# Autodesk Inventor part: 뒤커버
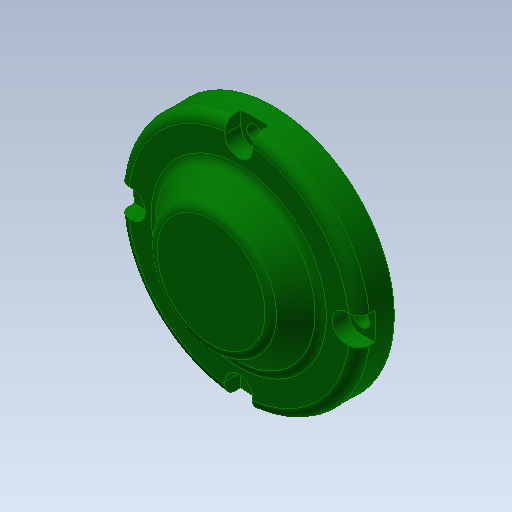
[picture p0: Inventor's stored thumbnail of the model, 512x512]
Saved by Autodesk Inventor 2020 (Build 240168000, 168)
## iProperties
Created: 2017-08
Part Number: 뒤커버
Material: 알루미늄 6061
Document SubType Name: Modeling
Designer: mduedu
Density: 1 g/cm^3
Appearance: 진녹색
Author: mduedu
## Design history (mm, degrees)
sketch "스케치1"
  geometry: C1 r 35 at (0, 0); 1 further point
  constraints: 1 centre point, 1 coincident
  dimensions: "d0" = 70 diameter of C1
extrude "돌출1" new body sketch "스케치1" distance "d1" = 10; taper "d2" = 0 deg
sketch "스케치2"
  geometry: C1 r 24 at (0, 0); 1 further point
  constraints: 1 centre point, 1 coincident
  dimensions: "d3" = 48 diameter of C1
node "작업 평면1"
sketch "스케치3"
  geometry: C1 r 17 at (0, 0); 1 further point
  constraints: 1 centre point, 1 coincident
  dimensions: "d5" = 34 diameter of C1
feature "로프트1" sketch "스케치3" dims "d6" = 0, "d7" = 90 deg, "d8" = 0, "d9" = 90 deg
sketch "스케치4"
  geometry: C1 r 24 at (0, 0) reference; 1 further point
extrude "돌출2" join sketch "스케치4" distance "d10" = 8; taper "d11" = 0 deg
hole "구멍1" diameter "d14" = 40; stored, may be unused: countersink angle "d18" = 90 deg, drill point angle "d20" = 0 deg; dims "d12" = 10, "d13" = 10, "d15" = 6, "d16" = 4, "d17" = 2, "d19" = 12
hole "구멍2" diameter "d23" = 34; stored, may be unused: countersink angle "d27" = 90 deg, drill point angle "d29" = 0 deg; dims "d24" = 6, "d25" = 4, "d26" = 2, "d28" = 6, "d62" = 10, "d63" = 10
chamfer "모따기1" distance "d39" = 1; stored, may be unused: second distance "d40" = 2, angle "d41" = 45 deg
fillet "모깎기1" dims "d42" = 0.3
fillet "모깎기2" dims "d43" = 3
fillet "모깎기3" dims "d56" = 3
sketch "스케치5" dims "d44" = 58
  geometry: 6 further points
  constraints: 2 vertical alignment, 1 coincident, 7 other
  dimensions: "d47" = 360 deg dimension on point (0, 0) point (0, 29) (derived)
sketch "스케치6" dims "d72" = 62
  geometry: C1 r 35 at (0, 0) reference; 2 further points
  constraints: 2 vertical alignment, 1 coincident, 2 other
hole "구멍4" sketch "스케치6" at (0, -31) diameter "d49" = 4.5; stored, may be unused: countersink angle "d53" = 90 deg, drill point angle "d55" = 0 deg; dims "d50" = 6, "d51" = 8, "d52" = 4.6, "d54" = 8
fillet "모깎기4" dims "d57" = 3
fillet "모깎기5" dims "d58" = 3
sketch "스케치7"
  geometry: L1 (-4, -31)-(4, -31); L2 (4, -31)-(4, -38); L3 (4, -38)-(-4, -38); L4 (-4, -38)-(-4, -31); 2 further points
  constraints: 8 end point, 2 parallel, 2 vertical, 1 horizontal, 1 midpoint, 1 perpendicular, 1 vertical alignment
  dimensions: "d65" = 7 distance of L1.end L2.end
extrude "돌출3" cut sketch "스케치7" stored distance "d67" = 10; taper "d68" = 0 deg
node "솔리드1"
pattern_circular "원형 패턴2" dims angle "d76" = 360 deg
pattern_circular "원형 패턴1" dims angle "d70" = 360 deg
other parameters: "d4" = 8
